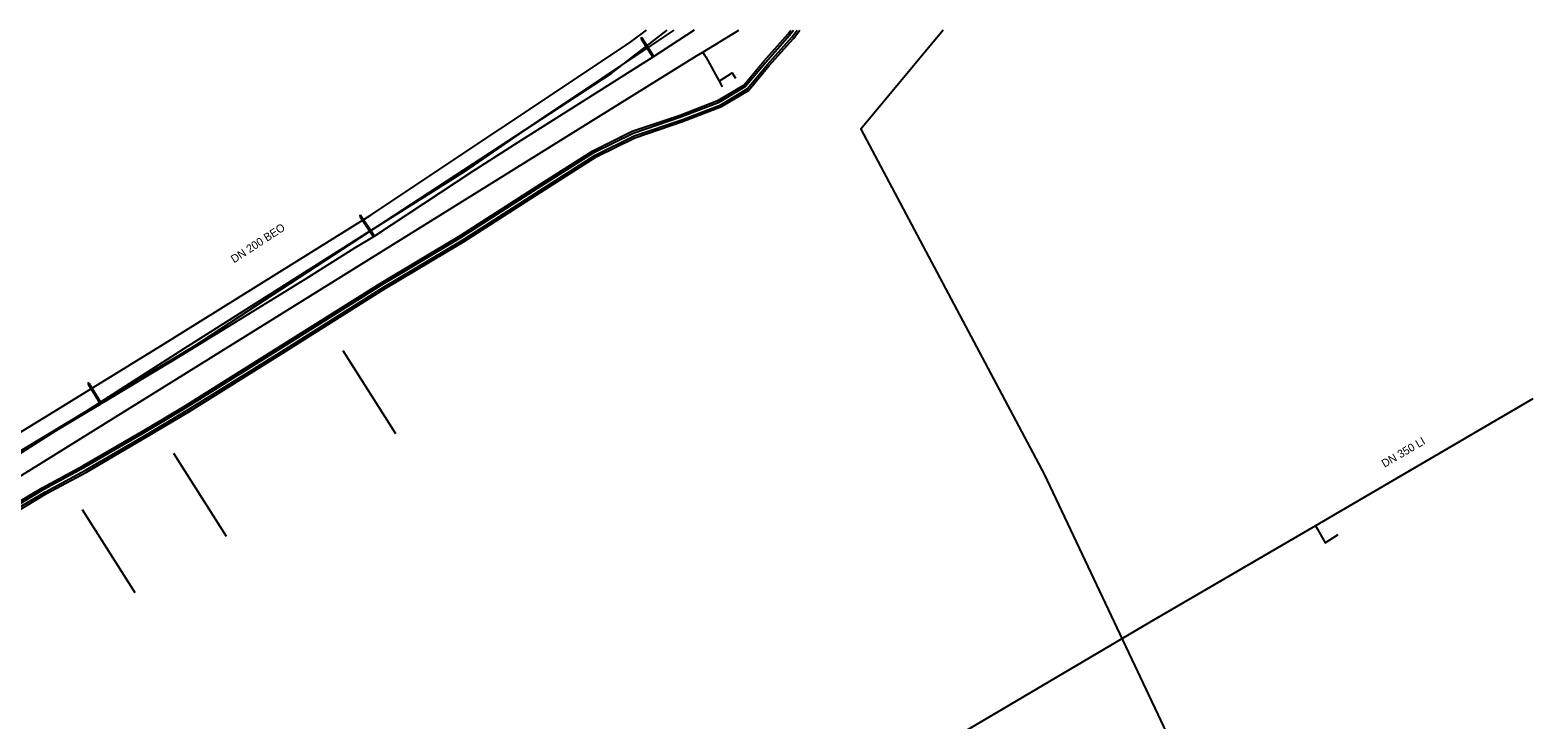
# Model space of a CAD drawing. Extents: x -600391 to -599491, y -1160176 to -1159402.
# Drawn here: x -599641 to -599490.8, y -1159470.7 to -1159401.8 of the extents above; entities that cross this region are included whole.
import ezdxf

# ---------------------------------------------------------------- set-up
doc = ezdxf.new("R2010")
doc.units = 0
for name, color, linetype in [('CETIN_linie', 7, 'Continuous'), ('Vrstva 1', 7, 'Continuous'), ('Vrstva 13', 7, 'Continuous'), ('Vrstva 15', 7, 'Continuous'), ('Vrstva 4', 7, 'Continuous'), ('Vrstva 44', 7, 'Continuous'), ('Vrstva 55', 7, 'Continuous'), ('Vrstva 58', 7, 'Continuous')]:
    doc.layers.add(name, color=color, linetype=linetype)

msp = doc.modelspace()

# ---------------------------------------------------------------- linework, layer by layer
at = {"layer": 'CETIN_linie'}
for points in [[(-599639.61, -1159440.54), (-599627.74, -1159433.24), (-599606.98, -1159420.31), (-599581.07, -1159403.05), (-599579.35, -1159401.77)], [(-599549.73, -1159401.77), (-599557.94, -1159411.69), (-599539.62, -1159446.15), (-599523.03, -1159481.23), (-599509.36, -1159513.77), (-599496.05, -1159546.71), (-599490.77, -1159561.12)], [(-599609.73, -1159433.81), (-599604.46, -1159442.1)], [(-599687.5, -1159469.87), (-599639.61, -1159440.54)], [(-599626.64, -1159444.07), (-599621.37, -1159452.36)], [(-599635.76, -1159449.68), (-599630.49, -1159457.97)]]:
    msp.add_lwpolyline(points, dxfattribs=at)
at = {"layer": 'Vrstva 1'}
msp.add_lwpolyline([(-599658.59, -1159453.85), (-599624.47, -1159433.28), (-599582.91, -1159406.12), (-599577.31, -1159401.77)], dxfattribs=at)
at = {"layer": 'Vrstva 13'}
for points in [[(-599757.93, -1159531.49), (-599760.55, -1159526.41), (-599759.42, -1159521.54), (-599758.81, -1159518.92), (-599742.22, -1159508.61), (-599680.74, -1159470.43), (-599612.05, -1159427.77), (-599574.38, -1159404.36), (-599573.73, -1159403.97), (-599570.13, -1159401.77)], [(-599573.73, -1159403.97), (-599573.53, -1159404.31), (-599573.45, -1159404.44), (-599572.12, -1159406.88), (-599571.81, -1159407.43)], [(-599572.12, -1159406.88), (-599570.82, -1159406.06), (-599570.47, -1159406.57)], [(-599490.77, -1159438.62), (-599512.51, -1159451.33), (-599529.09, -1159460.99), (-599704.29, -1159564.32), (-599711.49, -1159576.7), (-599713.26, -1159582)], [(-599512.51, -1159451.33), (-599512.32, -1159451.66), (-599511.54, -1159453.03), (-599510.24, -1159452.18)]]:
    msp.add_lwpolyline(points, dxfattribs=at)
at = {"layer": 'Vrstva 44'}
for points in [[(-599642.34, -1159449.78), (-599641.85, -1159449.37), (-599639.44, -1159447.92), (-599635.45, -1159445.76), (-599629.36, -1159442.22), (-599625.21, -1159439.74), (-599616.06, -1159434.03), (-599605.74, -1159427.52), (-599597.76, -1159422.76), (-599590.03, -1159417.81), (-599584.48, -1159414.27), (-599580.6, -1159412.35), (-599575.82, -1159410.73), (-599571.95, -1159409.24), (-599569.31, -1159407.65), (-599567.26, -1159405.2), (-599564.84, -1159402.48), (-599564.3, -1159401.77)], [(-599642.3, -1159449.87), (-599639.34, -1159448.1), (-599635.35, -1159445.94), (-599629.26, -1159442.4), (-599625.11, -1159439.91), (-599615.96, -1159434.19), (-599605.64, -1159427.69), (-599597.66, -1159422.92), (-599589.93, -1159417.97), (-599584.38, -1159414.45), (-599580.52, -1159412.53), (-599575.76, -1159410.91), (-599571.87, -1159409.42), (-599569.17, -1159407.81), (-599567.1, -1159405.32), (-599564.68, -1159402.6), (-599564.05, -1159401.77)]]:
    msp.add_lwpolyline(points, dxfattribs=at)
at = {"layer": 'Vrstva 55'}
msp.add_lwpolyline([(-599574.59, -1159401.77), (-599578.62, -1159404.41), (-599579.81, -1159402.58), (-599579.91, -1159402.53), (-599579.91, -1159402.65), (-599578.72, -1159404.47), (-599592.22, -1159413.02), (-599596.76, -1159415.89), (-599606.55, -1159422.37), (-599607.9, -1159420.35), (-599608, -1159420.3), (-599607.99, -1159420.42), (-599606.65, -1159422.43), (-599608.54, -1159423.58), (-599613.52, -1159426.71), (-599624.35, -1159433.35), (-599626.58, -1159434.73), (-599633.85, -1159439.09), (-599635.06, -1159437.08), (-599635.16, -1159437.03), (-599635.16, -1159437.15), (-599633.95, -1159439.15), (-599638.23, -1159441.71), (-599646.11, -1159446.64)], dxfattribs=at)
at = {"layer": 'Vrstva 58'}
for points in [[(-599576.65, -1159401.77), (-599577.72, -1159402.52), (-599590.09, -1159410.77), (-599597.7, -1159416.01), (-599608.01, -1159422.51), (-599625.61, -1159433.62), (-599645.63, -1159446.41)], [(-599642.65, -1159449.27), (-599639.69, -1159447.49), (-599635.69, -1159445.33), (-599629.62, -1159441.79), (-599625.47, -1159439.31), (-599616.33, -1159433.6), (-599606, -1159427.1), (-599598.03, -1159422.33), (-599590.3, -1159417.38), (-599584.72, -1159413.84), (-599580.79, -1159411.88), (-599575.99, -1159410.26), (-599572.17, -1159408.79), (-599569.64, -1159407.27), (-599567.63, -1159404.87), (-599565.22, -1159402.16), (-599564.93, -1159401.77)], [(-599642.55, -1159449.44), (-599639.59, -1159447.66), (-599635.6, -1159445.5), (-599629.51, -1159441.97), (-599625.37, -1159439.48), (-599616.22, -1159433.77), (-599605.9, -1159427.27), (-599597.92, -1159422.5), (-599590.2, -1159417.55), (-599584.63, -1159414.01), (-599580.71, -1159412.07), (-599575.93, -1159410.44), (-599572.09, -1159408.97), (-599569.5, -1159407.42), (-599567.48, -1159405), (-599565.07, -1159402.29), (-599564.68, -1159401.77)]]:
    msp.add_lwpolyline(points, dxfattribs=at)

# ---------------------------------------------------------------- texts
at = {"layer": 'Vrstva 15'}
msp.add_text('DN 350 LI', height=0.8, rotation=30.3095, dxfattribs=at).set_placement((-599505.61, -1159445.52))
at = {"layer": 'Vrstva 4'}
msp.add_text('DN 200 BEO', height=0.8, rotation=33.161, dxfattribs=at).set_placement((-599620.58, -1159425.09))

doc.saveas('drawing.dxf')
